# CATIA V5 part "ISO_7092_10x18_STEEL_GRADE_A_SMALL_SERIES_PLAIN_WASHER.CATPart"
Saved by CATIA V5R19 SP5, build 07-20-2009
Part number: ISO 7092 WASHER 10x18 STEEL GRADE A PLAIN SMALL SERIES
Publications: "Mating Face", "Axis"
Bounding box of the stored display mesh (mm): x 0 to 1, y -9 to 9, z -9 to 9
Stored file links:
  Z:\UA\ATLAS\atlascar\ServoPiloto\dir\suportePotenciometro\V2\ISO_7092_10x18_STEEL_GRADE_A_SMALL_SERIES_PLAIN_WASHER.CATPart
  Z:\programs_vbox\Dassault Systemes\B19\intel_a\startup\components\MechanicalStandardParts\ISO_Standards\Design_Tables\ISO_7092_PLAIN_WASHER_GRADE_A_SMALL_SERIES.txt
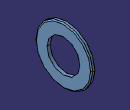
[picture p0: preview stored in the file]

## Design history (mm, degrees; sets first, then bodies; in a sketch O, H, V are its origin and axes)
Parameters
  d1_inside_dia = 10.5 mm
  d2_outside_dia = 18 mm
  h_max = 1 mm
  Nominal_dia = 10 mm
Body1 "PartBody" (main body)
  Sketch1 on yz-plane, origin (0, 0, 0), H (0, 1, 0), V (0, 0, 1)
    circle A1 centre (0, 0) radius 9
    circle A2 centre (0, 0) radius 5.25
    radius A1 = 9 {= d2_outside_dia /2}
    radius A2 = 5.25 {= d1_inside_dia /2}
  Pad1: profile Sketch1, direction (1, 0, 0), length 1 {= h_max}
  Chamfer1: length 0.375 {= 0.375*h_max}, angle 37.5, on edge [face of Pad1 | face of Pad1]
